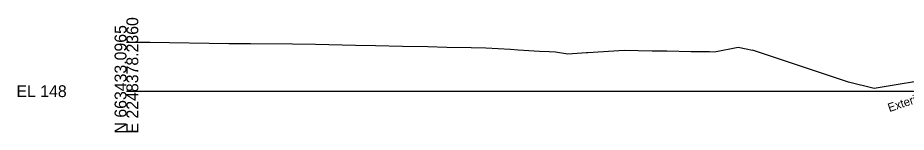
# Model space of a CAD drawing. Extents: x -26 to 2603, y -10 to 9566.
# Drawn here: x -25.7 to 184.4, y 8990.3 to 9017.3 of the extents above; entities that cross this region are included whole.
import ezdxf

# ---------------------------------------------------------------- set-up
doc = ezdxf.new("R2010")
doc.units = 0
for name, color, linetype in [('Default', 7, 'Continuous'), ('Exist Cross Section Cell', 7, 'Continuous'), ('Exist XS Ground Line', 7, 'Continuous'), ('Scratch_Level_9', 7, 'Continuous')]:
    doc.layers.add(name, color=color, linetype=linetype)

msp = doc.modelspace()

# ---------------------------------------------------------------- linework, layer by layer
at = {"layer": 'Exist Cross Section Cell'}
msp.add_line((0, 9000), (300, 9000), dxfattribs=at)
at = {"layer": 'Exist XS Ground Line'}
for p, q in [((0, 9011.57), (4.73, 9011.57)), ((4.73, 9011.57), (5.57, 9011.56)), ((5.57, 9011.56), (24.2, 9011.28)), ((24.2, 9011.28), (29.37, 9011.23)), ((29.37, 9011.23), (39.3, 9011.17)), ((39.3, 9011.17), (44.74, 9011.11)), ((44.74, 9011.11), (54.15, 9010.9)), ((54.15, 9010.9), (58.9, 9010.82)), ((58.9, 9010.82), (65.29, 9010.63)), ((65.29, 9010.63), (71.26, 9010.52)), ((71.26, 9010.52), (75.78, 9010.42)), ((75.78, 9010.42), (81.48, 9010.31)), ((81.48, 9010.31), (84.94, 9010.27)), ((84.94, 9010.27), (90.82, 9009.94)), ((90.82, 9009.94), (92.62, 9009.8)), ((92.62, 9009.8), (97.63, 9009.47)), ((139.04, 9009.33), (144.64, 9010.4)), ((144.64, 9010.4), (146.56, 9009.98)), ((146.56, 9009.98), (147.99, 9009.68)), ((97.63, 9009.47), (99.96, 9009.37)), ((99.96, 9009.37), (101.44, 9009.28)), ((101.44, 9009.28), (104.33, 9008.81)), ((104.33, 9008.81), (105.46, 9008.89)), ((105.46, 9008.89), (108.77, 9009.13)), ((108.77, 9009.13), (109.1, 9009.14)), ((109.1, 9009.14), (117.68, 9009.68)), ((117.68, 9009.68), (124.3, 9009.51)), ((124.3, 9009.51), (127.79, 9009.52)), ((127.79, 9009.52), (133.52, 9009.38)), ((133.52, 9009.38), (134.05, 9009.39)), ((134.05, 9009.39), (135.04, 9009.36)), ((135.04, 9009.36), (137.84, 9009.34)), ((137.84, 9009.34), (139.04, 9009.33))]:
    msp.add_line(p, q, dxfattribs=at)
for points in [[(176.77, 9000.64), (170.75, 9002.14), (147.99, 9009.68)], [(198.03, 9003.65), (192, 9003.17), (176.77, 9000.64)]]:
    msp.add_lwpolyline(points, dxfattribs=at)

# ---------------------------------------------------------------- texts
at = {"layer": 'Default'}
msp.add_text('-', height=0.0001, dxfattribs=at).set_placement((0, 9000))
msp.add_text('-', height=0.0001, dxfattribs=at).set_placement((0, 9000))
msp.add_text('-', height=0.0001, dxfattribs=at).set_placement((0, 9000))
at = {"layer": 'Exist Cross Section Cell'}
for s, p in [('E 2248378.2360', (2.8, 8990)), ('N 663433.0965', (0, 8990))]:
    msp.add_text(s, height=2.8, rotation=90, dxfattribs=at).set_placement(p)
msp.add_text('EL 148', height=2.8, dxfattribs=at).set_placement((-26, 8998.6))
at = {"layer": 'Scratch_Level_9'}
msp.add_text('Exterior Boundary', height=2, rotation=18.4332, dxfattribs=at).set_placement((180.41, 8995.06))

doc.saveas('drawing.dxf')
